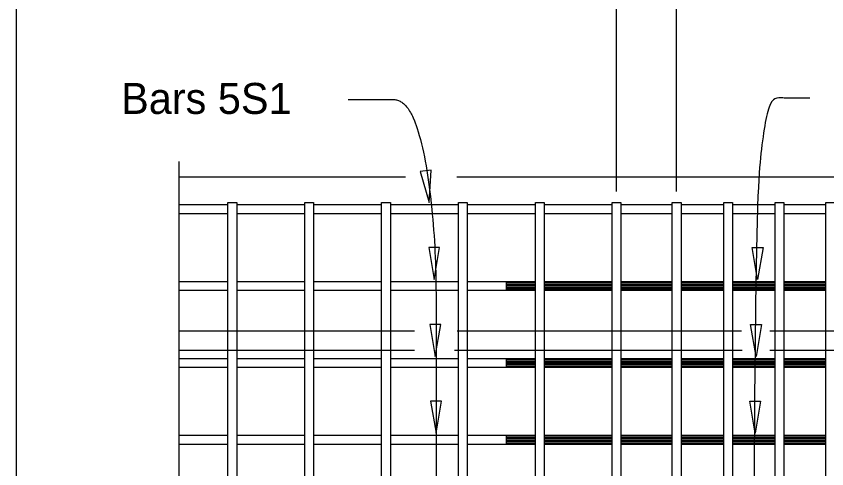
# Model space of a CAD drawing. Extents: x 120587.5 to 120659.6, y 120683.4 to 120715.5.
# Drawn here: x 120587.46 to 120592.74, y 120702.52 to 120705.47 of the extents above; entities that cross this region are included whole.
import ezdxf

# ---------------------------------------------------------------- set-up
doc = ezdxf.new("R2010")
doc.units = 0
for name, color, linetype in [('ActivePts-ConstElements', 7, 'Continuous'), ('AdhocPoint_dp', 7, 'Continuous'), ('Border', 7, 'Continuous'), ('PlotBorder_dp', 7, 'Continuous'), ('TextMisc', 7, 'Continuous')]:
    doc.layers.add(name, color=color, linetype=linetype)

msp = doc.modelspace()

# ---------------------------------------------------------------- linework, layer by layer
at = {"layer": 'ActivePts-ConstElements'}
msp.add_lwpolyline([(120587.4609, 120686.1476), (120628.5115, 120686.1476), (120628.5115, 120712.0937), (120587.4609, 120712.0937)], close=True, dxfattribs=at)
at = {"layer": 'AdhocPoint_dp'}
for p, q in [((120591.3674, 120704.3267), (120591.3674, 120706.3004)), ((120591.7581, 120704.3267), (120591.7581, 120706.3004))]:
    msp.add_line(p, q, dxfattribs=at)
msp.add_lwpolyline([(120588.5208, 120699.087), (120588.5208, 120701.3501), (120588.4174, 120701.3501), (120588.5208, 120701.3951), (120588.6241, 120701.4401), (120588.5208, 120701.4401), (120588.5208, 120704.5204)], dxfattribs=at)
for points in [[(120590.1489, 120704.2537), (120590.1602, 120704.4646), (120590.0901, 120704.4566)], [(120590.1802, 120703.7537), (120590.2155, 120703.962), (120590.145, 120703.962)], [(120592.2852, 120703.7537), (120592.25, 120703.962), (120592.3205, 120703.962)], [(120590.1878, 120703.2537), (120590.2231, 120703.462), (120590.1526, 120703.462)], [(120592.2752, 120703.2537), (120592.2399, 120703.462), (120592.3105, 120703.462)], [(120590.1927, 120702.7537), (120590.228, 120702.962), (120590.1575, 120702.962)], [(120592.2687, 120702.7537), (120592.2335, 120702.962), (120592.304, 120702.962)]]:
    msp.add_lwpolyline(points, close=True, dxfattribs=at)
for points in [[(120592.6255, 120704.9329), (120592.4825, 120704.9329), (120592.3336, 120704.9329), (120592.2561, 120703.9432), (120592.2563, 120699.7537)], [(120589.6208, 120704.924), (120589.7816, 120704.924), (120590.0497, 120704.924), (120590.1927, 120704.131), (120590.1927, 120703.1294), (120590.1927, 120699.7407)]]:
    msp.add_open_spline(points, degree=2, dxfattribs=at)
at = {"layer": 'Border'}
for p, q in [((120588.5208, 120704.2407), (120588.8388, 120704.2407)), ((120588.8961, 120704.2407), (120589.3388, 120704.2407)), ((120589.3961, 120704.2407), (120589.8388, 120704.2407)), ((120589.8961, 120704.2407), (120590.3388, 120704.2407)), ((120590.3961, 120704.2407), (120590.8388, 120704.2407)), ((120590.8961, 120704.2407), (120591.3388, 120704.2407)), ((120591.3961, 120704.2407), (120591.7294, 120704.2407)), ((120591.7867, 120704.2407), (120592.0653, 120704.2407)), ((120592.1226, 120704.2407), (120592.3987, 120704.2407)), ((120592.456, 120704.2407), (120592.7294, 120704.2407)), ((120588.5208, 120704.1834), (120588.8388, 120704.1834)), ((120588.8961, 120704.1834), (120589.3388, 120704.1834)), ((120589.3961, 120704.1834), (120589.8388, 120704.1834)), ((120589.8961, 120704.1834), (120590.3388, 120704.1834)), ((120590.3961, 120704.1834), (120590.8388, 120704.1834)), ((120590.8961, 120704.1834), (120591.3388, 120704.1834)), ((120591.3961, 120704.1834), (120591.7294, 120704.1834)), ((120591.7867, 120704.1834), (120592.0653, 120704.1834)), ((120592.1226, 120704.1834), (120592.3987, 120704.1834)), ((120592.456, 120704.1834), (120592.7294, 120704.1834)), ((120588.5208, 120703.7407), (120588.8388, 120703.7407)), ((120588.8961, 120703.7407), (120589.3388, 120703.7407)), ((120589.3961, 120703.7407), (120589.8388, 120703.7407)), ((120589.8961, 120703.7407), (120590.3388, 120703.7407)), ((120590.3961, 120703.7407), (120590.8388, 120703.7407)), ((120590.6487, 120703.7407), (120590.6487, 120703.6834)), ((120590.6487, 120703.7311), (120590.8388, 120703.7311)), ((120590.6487, 120703.7216), (120590.8388, 120703.7216)), ((120590.6487, 120703.712), (120590.8388, 120703.712)), ((120590.8961, 120703.7407), (120591.3388, 120703.7407)), ((120590.8961, 120703.7311), (120591.3388, 120703.7311)), ((120590.8961, 120703.7216), (120591.3388, 120703.7216)), ((120590.8961, 120703.712), (120591.3388, 120703.712)), ((120591.3961, 120703.7407), (120591.7294, 120703.7407)), ((120591.3961, 120703.7311), (120591.7294, 120703.7311)), ((120591.3961, 120703.7216), (120591.7294, 120703.7216)), ((120591.3961, 120703.712), (120591.7294, 120703.712)), ((120591.7867, 120703.7407), (120592.0653, 120703.7407)), ((120591.7867, 120703.7311), (120592.0653, 120703.7311)), ((120591.7867, 120703.7216), (120592.0653, 120703.7216)), ((120591.7867, 120703.712), (120592.0653, 120703.712)), ((120592.1226, 120703.7407), (120592.3987, 120703.7407)), ((120592.1226, 120703.7311), (120592.3987, 120703.7311)), ((120592.1226, 120703.7216), (120592.3987, 120703.7216)), ((120592.1226, 120703.712), (120592.3987, 120703.712)), ((120592.456, 120703.7407), (120592.7294, 120703.7407)), ((120592.456, 120703.7311), (120592.7294, 120703.7311)), ((120592.456, 120703.7216), (120592.7294, 120703.7216)), ((120592.456, 120703.712), (120592.7294, 120703.712)), ((120588.5208, 120703.6834), (120588.8388, 120703.6834)), ((120588.8961, 120703.6834), (120589.3388, 120703.6834)), ((120589.3961, 120703.6834), (120589.8388, 120703.6834)), ((120589.8961, 120703.6834), (120590.3388, 120703.6834)), ((120590.3961, 120703.6834), (120590.8388, 120703.6834)), ((120590.6487, 120703.7025), (120590.8388, 120703.7025)), ((120590.6487, 120703.6929), (120590.8388, 120703.6929)), ((120590.8961, 120703.7025), (120591.3388, 120703.7025)), ((120590.8961, 120703.6929), (120591.3388, 120703.6929)), ((120590.8961, 120703.6834), (120591.3388, 120703.6834)), ((120591.3961, 120703.7025), (120591.7294, 120703.7025)), ((120591.3961, 120703.6929), (120591.7294, 120703.6929)), ((120591.3961, 120703.6834), (120591.7294, 120703.6834)), ((120591.7867, 120703.7025), (120592.0653, 120703.7025)), ((120591.7867, 120703.6929), (120592.0653, 120703.6929)), ((120591.7867, 120703.6834), (120592.0653, 120703.6834)), ((120592.1226, 120703.7025), (120592.3987, 120703.7025)), ((120592.1226, 120703.6929), (120592.3987, 120703.6929)), ((120592.1226, 120703.6834), (120592.3987, 120703.6834)), ((120592.456, 120703.7025), (120592.7294, 120703.7025)), ((120592.456, 120703.6929), (120592.7294, 120703.6929)), ((120592.456, 120703.6834), (120592.7294, 120703.6834)), ((120588.5208, 120703.2407), (120588.8388, 120703.2407)), ((120588.8961, 120703.2407), (120589.3388, 120703.2407)), ((120589.3961, 120703.2407), (120589.8388, 120703.2407)), ((120589.8961, 120703.2407), (120590.3388, 120703.2407)), ((120590.3961, 120703.2407), (120590.8388, 120703.2407)), ((120590.6487, 120703.2407), (120590.6487, 120703.1834)), ((120590.8961, 120703.2407), (120591.3388, 120703.2407)), ((120591.3961, 120703.2407), (120591.7294, 120703.2407)), ((120591.7867, 120703.2407), (120592.0653, 120703.2407)), ((120592.1226, 120703.2407), (120592.3987, 120703.2407)), ((120592.456, 120703.2407), (120592.7294, 120703.2407)), ((120590.6487, 120703.2311), (120590.8388, 120703.2311)), ((120590.6487, 120703.2216), (120590.8388, 120703.2216)), ((120590.6487, 120703.212), (120590.8388, 120703.212)), ((120590.6487, 120703.2025), (120590.8388, 120703.2025)), ((120590.6487, 120703.1929), (120590.8388, 120703.1929)), ((120590.8961, 120703.2311), (120591.3388, 120703.2311)), ((120590.8961, 120703.2216), (120591.3388, 120703.2216)), ((120590.8961, 120703.212), (120591.3388, 120703.212)), ((120590.8961, 120703.2025), (120591.3388, 120703.2025)), ((120590.8961, 120703.1929), (120591.3388, 120703.1929)), ((120591.3961, 120703.2311), (120591.7294, 120703.2311)), ((120591.3961, 120703.2216), (120591.7294, 120703.2216)), ((120591.3961, 120703.212), (120591.7294, 120703.212)), ((120591.3961, 120703.2025), (120591.7294, 120703.2025)), ((120591.3961, 120703.1929), (120591.7294, 120703.1929)), ((120591.7867, 120703.2311), (120592.0653, 120703.2311)), ((120591.7867, 120703.2216), (120592.0653, 120703.2216)), ((120591.7867, 120703.212), (120592.0653, 120703.212)), ((120591.7867, 120703.2025), (120592.0653, 120703.2025)), ((120591.7867, 120703.1929), (120592.0653, 120703.1929)), ((120592.1226, 120703.2311), (120592.3987, 120703.2311)), ((120592.1226, 120703.2216), (120592.3987, 120703.2216)), ((120592.1226, 120703.212), (120592.3987, 120703.212)), ((120592.1226, 120703.2025), (120592.3987, 120703.2025)), ((120592.1226, 120703.1929), (120592.3987, 120703.1929)), ((120592.456, 120703.2311), (120592.7294, 120703.2311)), ((120592.456, 120703.2216), (120592.7294, 120703.2216)), ((120592.456, 120703.212), (120592.7294, 120703.212)), ((120592.456, 120703.2025), (120592.7294, 120703.2025)), ((120592.456, 120703.1929), (120592.7294, 120703.1929)), ((120588.5208, 120703.1834), (120588.8388, 120703.1834)), ((120588.8961, 120703.1834), (120589.3388, 120703.1834)), ((120589.3961, 120703.1834), (120589.8388, 120703.1834)), ((120589.8961, 120703.1834), (120590.3388, 120703.1834)), ((120590.3961, 120703.1834), (120590.8388, 120703.1834)), ((120590.8961, 120703.1834), (120591.3388, 120703.1834)), ((120591.3961, 120703.1834), (120591.7294, 120703.1834)), ((120591.7867, 120703.1834), (120592.0653, 120703.1834)), ((120592.1226, 120703.1834), (120592.3987, 120703.1834)), ((120592.456, 120703.1834), (120592.7294, 120703.1834)), ((120588.5208, 120702.7407), (120588.8388, 120702.7407)), ((120588.8961, 120702.7407), (120589.3388, 120702.7407)), ((120589.3961, 120702.7407), (120589.8388, 120702.7407)), ((120589.8961, 120702.7407), (120590.3388, 120702.7407)), ((120590.3961, 120702.7407), (120590.8388, 120702.7407)), ((120590.6487, 120702.7407), (120590.6487, 120702.6834)), ((120590.6487, 120702.7311), (120590.8388, 120702.7311)), ((120590.6487, 120702.7216), (120590.8388, 120702.7216)), ((120590.6487, 120702.712), (120590.8388, 120702.712)), ((120590.8961, 120702.7407), (120591.3388, 120702.7407)), ((120590.8961, 120702.7311), (120591.3388, 120702.7311)), ((120590.8961, 120702.7216), (120591.3388, 120702.7216)), ((120590.8961, 120702.712), (120591.3388, 120702.712)), ((120591.3961, 120702.7407), (120591.7294, 120702.7407)), ((120591.3961, 120702.7311), (120591.7294, 120702.7311)), ((120591.3961, 120702.7216), (120591.7294, 120702.7216)), ((120591.3961, 120702.712), (120591.7294, 120702.712)), ((120591.7867, 120702.7407), (120592.0653, 120702.7407)), ((120591.7867, 120702.7311), (120592.0653, 120702.7311)), ((120591.7867, 120702.7216), (120592.0653, 120702.7216)), ((120591.7867, 120702.712), (120592.0653, 120702.712)), ((120592.1226, 120702.7407), (120592.3987, 120702.7407)), ((120592.1226, 120702.7311), (120592.3987, 120702.7311)), ((120592.1226, 120702.7216), (120592.3987, 120702.7216)), ((120592.1226, 120702.712), (120592.3987, 120702.712)), ((120592.456, 120702.7407), (120592.7294, 120702.7407)), ((120592.456, 120702.7311), (120592.7294, 120702.7311)), ((120592.456, 120702.7216), (120592.7294, 120702.7216)), ((120592.456, 120702.712), (120592.7294, 120702.712)), ((120588.5208, 120702.6834), (120588.8388, 120702.6834)), ((120588.8961, 120702.6834), (120589.3388, 120702.6834)), ((120589.3961, 120702.6834), (120589.8388, 120702.6834)), ((120589.8961, 120702.6834), (120590.3388, 120702.6834)), ((120590.3961, 120702.6834), (120590.8388, 120702.6834)), ((120590.6487, 120702.7025), (120590.8388, 120702.7025)), ((120590.6487, 120702.6929), (120590.8388, 120702.6929)), ((120590.8961, 120702.7025), (120591.3388, 120702.7025)), ((120590.8961, 120702.6929), (120591.3388, 120702.6929)), ((120590.8961, 120702.6834), (120591.3388, 120702.6834)), ((120591.3961, 120702.7025), (120591.7294, 120702.7025)), ((120591.3961, 120702.6929), (120591.7294, 120702.6929)), ((120591.3961, 120702.6834), (120591.7294, 120702.6834)), ((120591.7867, 120702.7025), (120592.0653, 120702.7025)), ((120591.7867, 120702.6929), (120592.0653, 120702.6929)), ((120591.7867, 120702.6834), (120592.0653, 120702.6834)), ((120592.1226, 120702.7025), (120592.3987, 120702.7025)), ((120592.1226, 120702.6929), (120592.3987, 120702.6929)), ((120592.1226, 120702.6834), (120592.3987, 120702.6834)), ((120592.456, 120702.7025), (120592.7294, 120702.7025)), ((120592.456, 120702.6929), (120592.7294, 120702.6929)), ((120592.456, 120702.6834), (120592.7294, 120702.6834))]:
    msp.add_line(p, q, dxfattribs=at)
for points in [[(120588.8388, 120704.2537), (120588.8961, 120704.2537), (120588.8961, 120696.4203), (120588.8388, 120696.4203)], [(120589.3388, 120704.2537), (120589.3961, 120704.2537), (120589.3961, 120696.4203), (120589.3388, 120696.4203)], [(120589.8388, 120704.2537), (120589.8961, 120704.2537), (120589.8961, 120696.4203), (120589.8388, 120696.4203)], [(120590.3388, 120704.2537), (120590.3961, 120704.2537), (120590.3961, 120696.4203), (120590.3388, 120696.4203)], [(120590.8388, 120704.2537), (120590.8961, 120704.2537), (120590.8961, 120696.4203), (120590.8388, 120696.4203)], [(120591.3388, 120704.2537), (120591.3961, 120704.2537), (120591.3961, 120696.4204), (120591.3388, 120696.4204)], [(120591.7294, 120704.2537), (120591.7867, 120704.2537), (120591.7867, 120696.4204), (120591.7294, 120696.4204)], [(120592.0653, 120704.2537), (120592.1226, 120704.2537), (120592.1226, 120696.4204), (120592.0653, 120696.4204)], [(120592.3987, 120704.2537), (120592.456, 120704.2537), (120592.456, 120696.4204), (120592.3987, 120696.4204)], [(120592.7294, 120704.2537), (120592.7867, 120704.2537), (120592.7867, 120696.4204), (120592.7294, 120696.4204)]]:
    msp.add_lwpolyline(points, close=True, dxfattribs=at)
at = {"layer": 'PlotBorder_dp'}
for p, q in [((120588.5208, 120704.4203), (120589.9943, 120704.4203)), ((120590.328, 120704.4203), (120597.939, 120704.4203)), ((120588.5208, 120703.4203), (120590.0532, 120703.4203)), ((120590.3299, 120703.4203), (120592.1798, 120703.4203)), ((120592.3653, 120703.4203), (120598.0015, 120703.4203)), ((120588.5208, 120703.2953), (120590.0532, 120703.2953)), ((120590.3123, 120703.2953), (120592.1854, 120703.2953)), ((120592.3653, 120703.2953), (120598.0015, 120703.2953))]:
    msp.add_line(p, q, dxfattribs=at)
at = {"layer": 'TextMisc'}
for p, q in [((120588.5208, 120704.1834), (120588.5208, 120704.2407)), ((120588.5208, 120703.6834), (120588.5208, 120703.7407)), ((120588.5208, 120703.1834), (120588.5208, 120703.2407)), ((120588.5208, 120702.6834), (120588.5208, 120702.7407))]:
    msp.add_line(p, q, dxfattribs=at)

# ---------------------------------------------------------------- texts
msp.add_text('Bars 5S1', height=0.2016, dxfattribs=at).set_placement((120588.1436, 120704.83))

doc.saveas('drawing.dxf')
